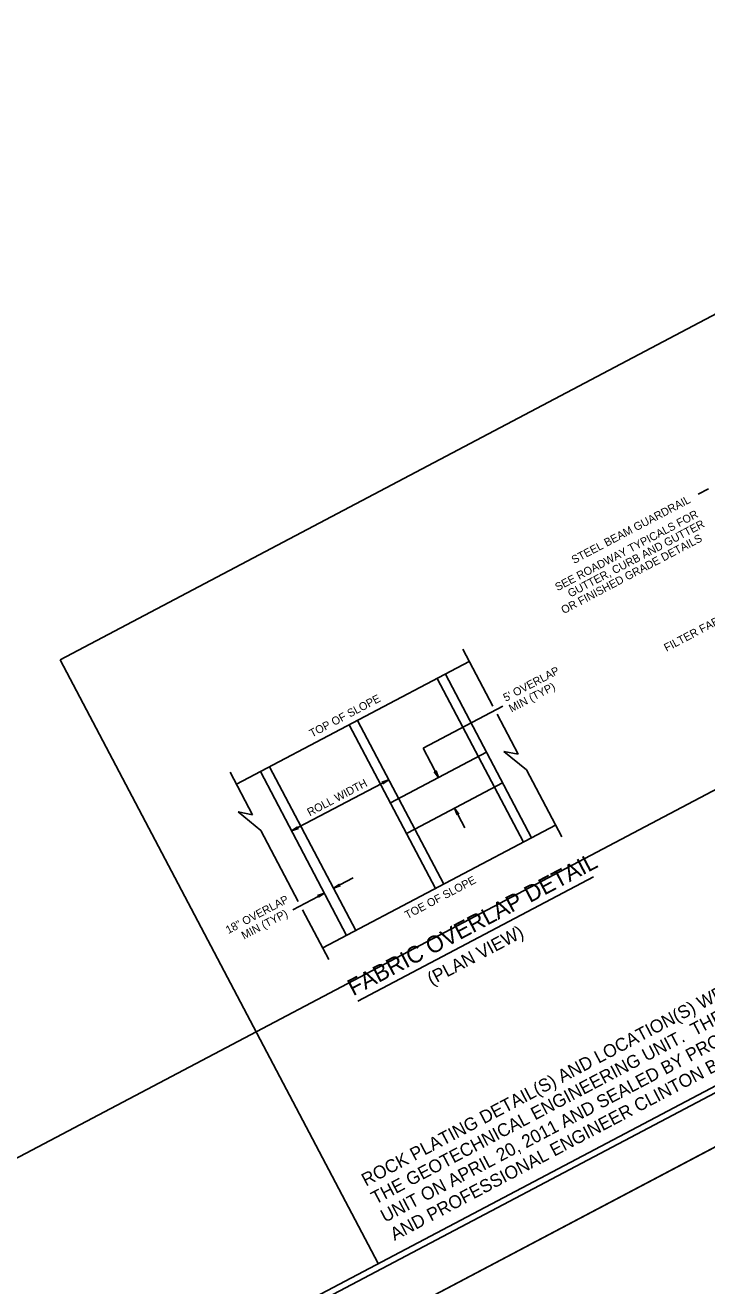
# Model space of a CAD drawing. Extents: x 1380651 to 1383136, y 594581 to 596344.
# Drawn here: x 1381741 to 1382027, y 594981 to 595509 of the extents above; entities that cross this region are included whole.
import ezdxf

# ---------------------------------------------------------------- set-up
doc = ezdxf.new("R2010")
doc.units = 0
for name, color, linetype in [('Prop Geotechnical Rock Plating Detail CELL', 7, 'Continuous'), ('Sheet Clip Boundary CELL', 7, 'Continuous'), ('Sheet Cutting Line CELL', 7, 'Continuous'), ('Sheet Layout Plan Border', 7, 'Continuous'), ('Sheet Plan CELL', 7, 'Continuous'), ('Sheet Plot Border Inside CELL', 7, 'Continuous'), ('Sheet Plot Border Outside CELL', 7, 'Continuous')]:
    doc.layers.add(name, color=color, linetype=linetype)

msp = doc.modelspace()

# ---------------------------------------------------------------- linework, layer by layer
at = {"layer": 'Prop Geotechnical Rock Plating Detail CELL'}
for p, q in [((1381755.38, 595243.47), (1382226.32, 595491.74)), ((1382023, 595312.78), (1382027.3, 595315.04)), ((1381936.86, 595224), (1381924.3, 595247.82)), ((1381755.38, 595243.47), (1381888.82, 594990.36)), ((1381926.98, 595242.74), (1381829.34, 595191.27)), ((1381913.52, 595235.64), (1381949.69, 595167.03)), ((1381916.94, 595237.45), (1381953.11, 595168.84)), ((1381940.98, 595224), (1381907.58, 595206.39)), ((1381938.65, 595220.61), (1381947.43, 595203.93)), ((1381876.66, 595216.21), (1381912.83, 595147.6)), ((1381880.07, 595218.01), (1381916.25, 595149.4)), ((1381934.23, 595204.66), (1381893.94, 595183.43)), ((1381907.58, 595206.39), (1381914.09, 595194.05)), ((1381947.43, 595203.93), (1381941.49, 595205.06)), ((1381941.49, 595205.06), (1381950.93, 595197.28)), ((1381843.21, 595198.58), (1381879.38, 595129.96)), ((1381826.67, 595196.35), (1381836.06, 595178.52)), ((1381839.37, 595196.55), (1381875.54, 595127.94)), ((1381852.47, 595171.71), (1381893.17, 595193.16)), ((1381893.17, 595193.16), (1381890.3, 595192.11)), ((1381890.38, 595192.09), (1381893.17, 595193.16)), ((1381893.17, 595193.16), (1381890.46, 595192.06)), ((1381890.53, 595192.04), (1381893.17, 595193.16)), ((1381893.17, 595193.16), (1381890.61, 595192.01)), ((1381893.17, 595193.16), (1381890.68, 595191.39)), ((1381890.68, 595191.99), (1381893.17, 595193.16)), ((1381893.17, 595193.16), (1381890.71, 595191.47)), ((1381890.73, 595191.54), (1381893.17, 595193.16)), ((1381893.17, 595193.16), (1381890.75, 595191.62)), ((1381893.17, 595193.16), (1381890.76, 595191.96)), ((1381890.78, 595191.7), (1381893.17, 595193.16)), ((1381893.17, 595193.16), (1381890.79, 595191.78)), ((1381890.82, 595191.86), (1381893.17, 595193.16)), ((1381890.84, 595191.93), (1381893.17, 595193.16)), ((1381914.09, 595194.05), (1381912.31, 595196.53)), ((1381912.31, 595196.53), (1381912.86, 595196.38)), ((1381912.39, 595196.51), (1381914.09, 595194.05)), ((1381914.09, 595194.05), (1381912.47, 595196.49)), ((1381912.54, 595196.47), (1381914.09, 595194.05)), ((1381914.09, 595194.05), (1381912.63, 595196.44)), ((1381912.7, 595196.42), (1381914.09, 595194.05)), ((1381914.09, 595194.05), (1381912.78, 595196.4)), ((1381912.86, 595196.38), (1381913.03, 595196.91)), ((1381912.86, 595196.38), (1381914.09, 595194.05)), ((1381912.88, 595196.45), (1381914.09, 595194.05)), ((1381914.09, 595194.05), (1381912.9, 595196.53)), ((1381912.93, 595196.6), (1381914.09, 595194.05)), ((1381914.09, 595194.05), (1381912.96, 595196.69)), ((1381912.99, 595196.76), (1381914.09, 595194.05)), ((1381914.09, 595194.05), (1381913.01, 595196.84)), ((1381914.09, 595194.05), (1381913.03, 595196.91)), ((1381950.93, 595197.28), (1381965.74, 595169.19)), ((1381890.3, 595192.11), (1381890.84, 595191.93)), ((1381890.84, 595191.93), (1381890.68, 595191.39)), ((1381940.96, 595191.89), (1381904.09, 595172.45)), ((1381836.06, 595178.52), (1381830.13, 595179.65)), ((1381830.13, 595179.65), (1381839.57, 595171.87)), ((1381920.82, 595181.27), (1381921.88, 595178.4)), ((1381920.82, 595181.27), (1381922.6, 595178.78)), ((1381922.52, 595178.8), (1381920.82, 595181.27)), ((1381920.82, 595181.27), (1381922.44, 595178.83)), ((1381922.36, 595178.85), (1381920.82, 595181.27)), ((1381920.82, 595181.27), (1381922.28, 595178.87)), ((1381922.21, 595178.89), (1381920.82, 595181.27)), ((1381920.82, 595181.27), (1381922.13, 595178.92)), ((1381922.05, 595178.94), (1381920.82, 595181.27)), ((1381922.03, 595178.86), (1381920.82, 595181.27)), ((1381920.82, 595181.27), (1381922, 595178.78)), ((1381921.98, 595178.71), (1381920.82, 595181.27)), ((1381920.82, 595181.27), (1381921.95, 595178.63)), ((1381921.92, 595178.55), (1381920.82, 595181.27)), ((1381920.82, 595181.27), (1381921.9, 595178.48)), ((1381925.16, 595173.05), (1381920.82, 595181.27)), ((1381922.05, 595178.94), (1381921.88, 595178.4)), ((1381922.6, 595178.78), (1381922.05, 595178.94)), ((1381852.47, 595171.71), (1381854.96, 595173.48)), ((1381852.47, 595171.71), (1381854.94, 595173.4)), ((1381854.91, 595173.33), (1381852.47, 595171.71)), ((1381852.47, 595171.71), (1381854.89, 595173.25)), ((1381854.87, 595173.17), (1381852.47, 595171.71)), ((1381852.47, 595171.71), (1381854.85, 595173.09)), ((1381854.83, 595173.01), (1381852.47, 595171.71)), ((1381854.81, 595172.94), (1381852.47, 595171.71)), ((1381852.47, 595171.71), (1381854.88, 595172.91)), ((1381854.96, 595172.88), (1381852.47, 595171.71)), ((1381852.47, 595171.71), (1381855.03, 595172.86)), ((1381855.11, 595172.83), (1381852.47, 595171.71)), ((1381852.47, 595171.71), (1381855.19, 595172.81)), ((1381855.27, 595172.78), (1381852.47, 595171.71)), ((1381852.47, 595171.71), (1381855.34, 595172.75)), ((1381854.81, 595172.94), (1381854.96, 595173.48)), ((1381855.34, 595172.75), (1381854.81, 595172.94)), ((1381865.52, 595122.65), (1381963.14, 595174.12)), ((1381904.09, 595172.45), (1381900.68, 595170.65)), ((1381839.57, 595171.87), (1381855.27, 595142.08)), ((1381870.03, 595147.69), (1381878.25, 595152.03)), ((1381979.04, 595152.48), (1381880.18, 595100.36)), ((1381866.2, 595145.67), (1381852.94, 595138.68)), ((1381866.2, 595145.67), (1381863.33, 595144.62)), ((1381863.4, 595144.6), (1381866.2, 595145.67)), ((1381866.2, 595145.67), (1381863.48, 595144.57)), ((1381863.56, 595144.55), (1381866.2, 595145.67)), ((1381866.2, 595145.67), (1381863.64, 595144.52)), ((1381866.2, 595145.67), (1381863.71, 595143.9)), ((1381863.71, 595144.49), (1381866.2, 595145.67)), ((1381866.2, 595145.67), (1381863.73, 595143.98)), ((1381863.76, 595144.05), (1381866.2, 595145.67)), ((1381866.2, 595145.67), (1381863.78, 595144.13)), ((1381866.2, 595145.67), (1381863.79, 595144.47)), ((1381863.8, 595144.21), (1381866.2, 595145.67)), ((1381866.2, 595145.67), (1381863.82, 595144.29)), ((1381863.84, 595144.37), (1381866.2, 595145.67)), ((1381863.86, 595144.44), (1381866.2, 595145.67)), ((1381870.03, 595147.69), (1381872.52, 595149.46)), ((1381870.03, 595147.69), (1381872.5, 595149.39)), ((1381872.47, 595149.31), (1381870.03, 595147.69)), ((1381870.03, 595147.69), (1381872.45, 595149.23)), ((1381872.43, 595149.15), (1381870.03, 595147.69)), ((1381870.03, 595147.69), (1381872.41, 595149.08)), ((1381872.39, 595149), (1381870.03, 595147.69)), ((1381872.36, 595148.92), (1381870.03, 595147.69)), ((1381870.03, 595147.69), (1381872.44, 595148.89)), ((1381872.52, 595148.87), (1381870.03, 595147.69)), ((1381870.03, 595147.69), (1381872.59, 595148.85)), ((1381872.67, 595148.82), (1381870.03, 595147.69)), ((1381870.03, 595147.69), (1381872.75, 595148.79)), ((1381872.83, 595148.77), (1381870.03, 595147.69)), ((1381870.03, 595147.69), (1381872.9, 595148.74)), ((1381872.36, 595148.92), (1381872.52, 595149.46)), ((1381872.9, 595148.74), (1381872.36, 595148.92)), ((1381863.33, 595144.62), (1381863.86, 595144.44)), ((1381863.86, 595144.44), (1381863.71, 595143.9)), ((1381857.06, 595138.69), (1381868.06, 595117.84))]:
    msp.add_line(p, q, dxfattribs=at)
at = {"layer": 'Sheet Clip Boundary CELL'}
msp.add_lwpolyline([(1381254.23, 594780.01), (1382566.26, 595471.7), (1382154.39, 596252.97), (1381978.55, 596160.27), (1381909.21, 596291.79), (1380773.01, 595692.8)], close=True, dxfattribs=at)
at = {"layer": 'Sheet Cutting Line CELL'}
msp.add_line((1381161.45, 594581.45), (1382650.68, 595366.55), dxfattribs=at)
at = {"layer": 'Sheet Layout Plan Border'}
msp.add_lwpolyline([(1381298.21, 594679), (1382625.14, 595378.54), (1382205.45, 596174.64), (1382028.49, 596081.35), (1381958.53, 596214.06), (1380808.55, 595607.8)], close=True, dxfattribs=at)
at = {"layer": 'Sheet Plan CELL'}
for points in [[(1382135.49, 596307.38), (1380808.56, 595607.84), (1381298.23, 594679.01), (1382625.14, 595378.54)], [(1381298.23, 594679.01), (1380808.55, 595607.8), (1381958.5, 596214.09), (1382028.49, 596081.35), (1382205.45, 596174.63), (1382625.14, 595378.54)]]:
    msp.add_lwpolyline(points, close=True, dxfattribs=at)
at = {"layer": 'Sheet Plot Border Inside CELL'}
msp.add_lwpolyline([(1381163.62, 594605.21), (1382637.35, 595382.15), (1382145.37, 596315.4), (1380671.62, 595538.46)], close=True, dxfattribs=at)
at = {"layer": 'Sheet Plot Border Outside CELL'}
msp.add_lwpolyline([(1381161.45, 594581.45), (1382650.68, 595366.55), (1382140.02, 596335.19), (1380650.8, 595550.09)], close=True, dxfattribs=at)

# ---------------------------------------------------------------- texts
at = {"layer": 'Prop Geotechnical Rock Plating Detail CELL'}
for s, height, p in [('STEEL BEAM GUARDRAIL', 3.3528, (1381970.92, 595283.56)), ('SEE ROADWAY TYPICALS FOR', 3.3528, (1381964.02, 595272.15)), ('GUTTER, CURB AND GUTTER', 3.3528, (1381969.36, 595269.48)), ('OR FINISHED GRADE DETAILS', 3.3528, (1381966.58, 595262.53)), ('FILTER FABRIC FOR ROCK PLATING', 3.3528, (1382009.69, 595246.74)), ("5' OVERLAP", 3.353, (1381942.28, 595225.81)), ('MIN (TYP)', 3.353, (1381944.66, 595221.29)), ('TOP OF SLOPE', 3.3528, (1381861.01, 595210.82)), ('ROLL WIDTH', 3.353, (1381860.09, 595177.77)), ('ROCK PLATING DETAIL(S) AND LOCATION(S) WERE PROVIDED THROUGH A SEALED DOCUMENT FROM', 5.4175, (1381883.61, 595022.65)), ('UNIT ON APRIL 20, 2011 AND SEALED BY PROFESSIONAL ENGINEER, JOHN S. W. FARGHER III, LICENSE #023480.', 5.4175, (1381891.62, 595007.45)), ('THE GEOTECHNICAL ENGINEERING UNIT.  THE DOCUMENT WAS SUBMITTED TO THE ROADWAY DESIGN', 5.4175, (1381887.62, 595015.05)), ('FABRIC OVERLAP DETAIL', 7, (1381878.31, 595102.38)), ('TOE OF SLOPE', 3.3528, (1381901.01, 595134.72)), ('18" OVERLAP', 3.3528, (1381825.93, 595128.45)), ('MIN (TYP)', 3.353, (1381832.51, 595126.15)), ('(PLAN VIEW)', 5.4175, (1381911.17, 595106.9)), ('AND PROFESSIONAL ENGINEER CLINTON B. LITTLE, LICENSE #1104', 5.4175, (1381895.63, 594999.85))]:
    msp.add_text(s, height=height, rotation=27.7977, dxfattribs=at).set_placement(p)

doc.saveas('drawing.dxf')
